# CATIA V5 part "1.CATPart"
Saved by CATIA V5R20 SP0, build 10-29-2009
Part number: 1
Bounding box of the stored display mesh (mm): x -259.502 to 259.5, y -258.017 to 260, z -60 to 60
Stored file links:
  E:\Ehsan\Amoozesh\CATIA\CATIA Course\Advanced\Videos\Session-24\1.CATPart
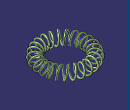
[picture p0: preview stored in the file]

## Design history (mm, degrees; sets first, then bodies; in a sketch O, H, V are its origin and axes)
Parameters
  LENGTH = 0 mm
  LENGTH = 0 mm
  LENGTH = 0 mm
AxisSystem1: origin (0, 0, 0), X (1, 0, 0), Y (0, 1, 0), Z (0, 0, 1)
Set1
  Extrude1: Lim1 30, Lim2 0, Element1 Sketch2
  Sketch1 on XY plane of AxisSystem1, origin (0, 0, 0), H (0, 1, 0), V (-1, 0, 0)
    circle A1 centre (252.5, 0) radius 7.5
    point P1 (252.5, 0)
    reference projected circle E1 centre (0, 0) radius 200 from Sketch2.A1
    radius A1 = 7.5
    distance E1 A1 = 45
    coincidence: P1 H
  Sweep1: type Unspec, Profile Sketch1, Guide Sketch2, Reference Extrude1, RefAngle 9000, RefAngle2 0
Body1 (main body)
  Sketch2 on XY plane of AxisSystem1, origin (0, 0, 0), H (0, 1, 0), V (-1, 0, 0)
    circle A1 centre (0, 0) radius 200
    radius A1 = 200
